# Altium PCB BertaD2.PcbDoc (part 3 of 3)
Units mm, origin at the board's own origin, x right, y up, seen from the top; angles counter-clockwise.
Board outline 100.5 x 100 mm, 4 copper layers (Top Layer, Signal Layer 1, Signal Layer 2, Bottom Layer), stack 0.778 mm thick; 108 components, 216 nets, 850 pads, 807 vias.
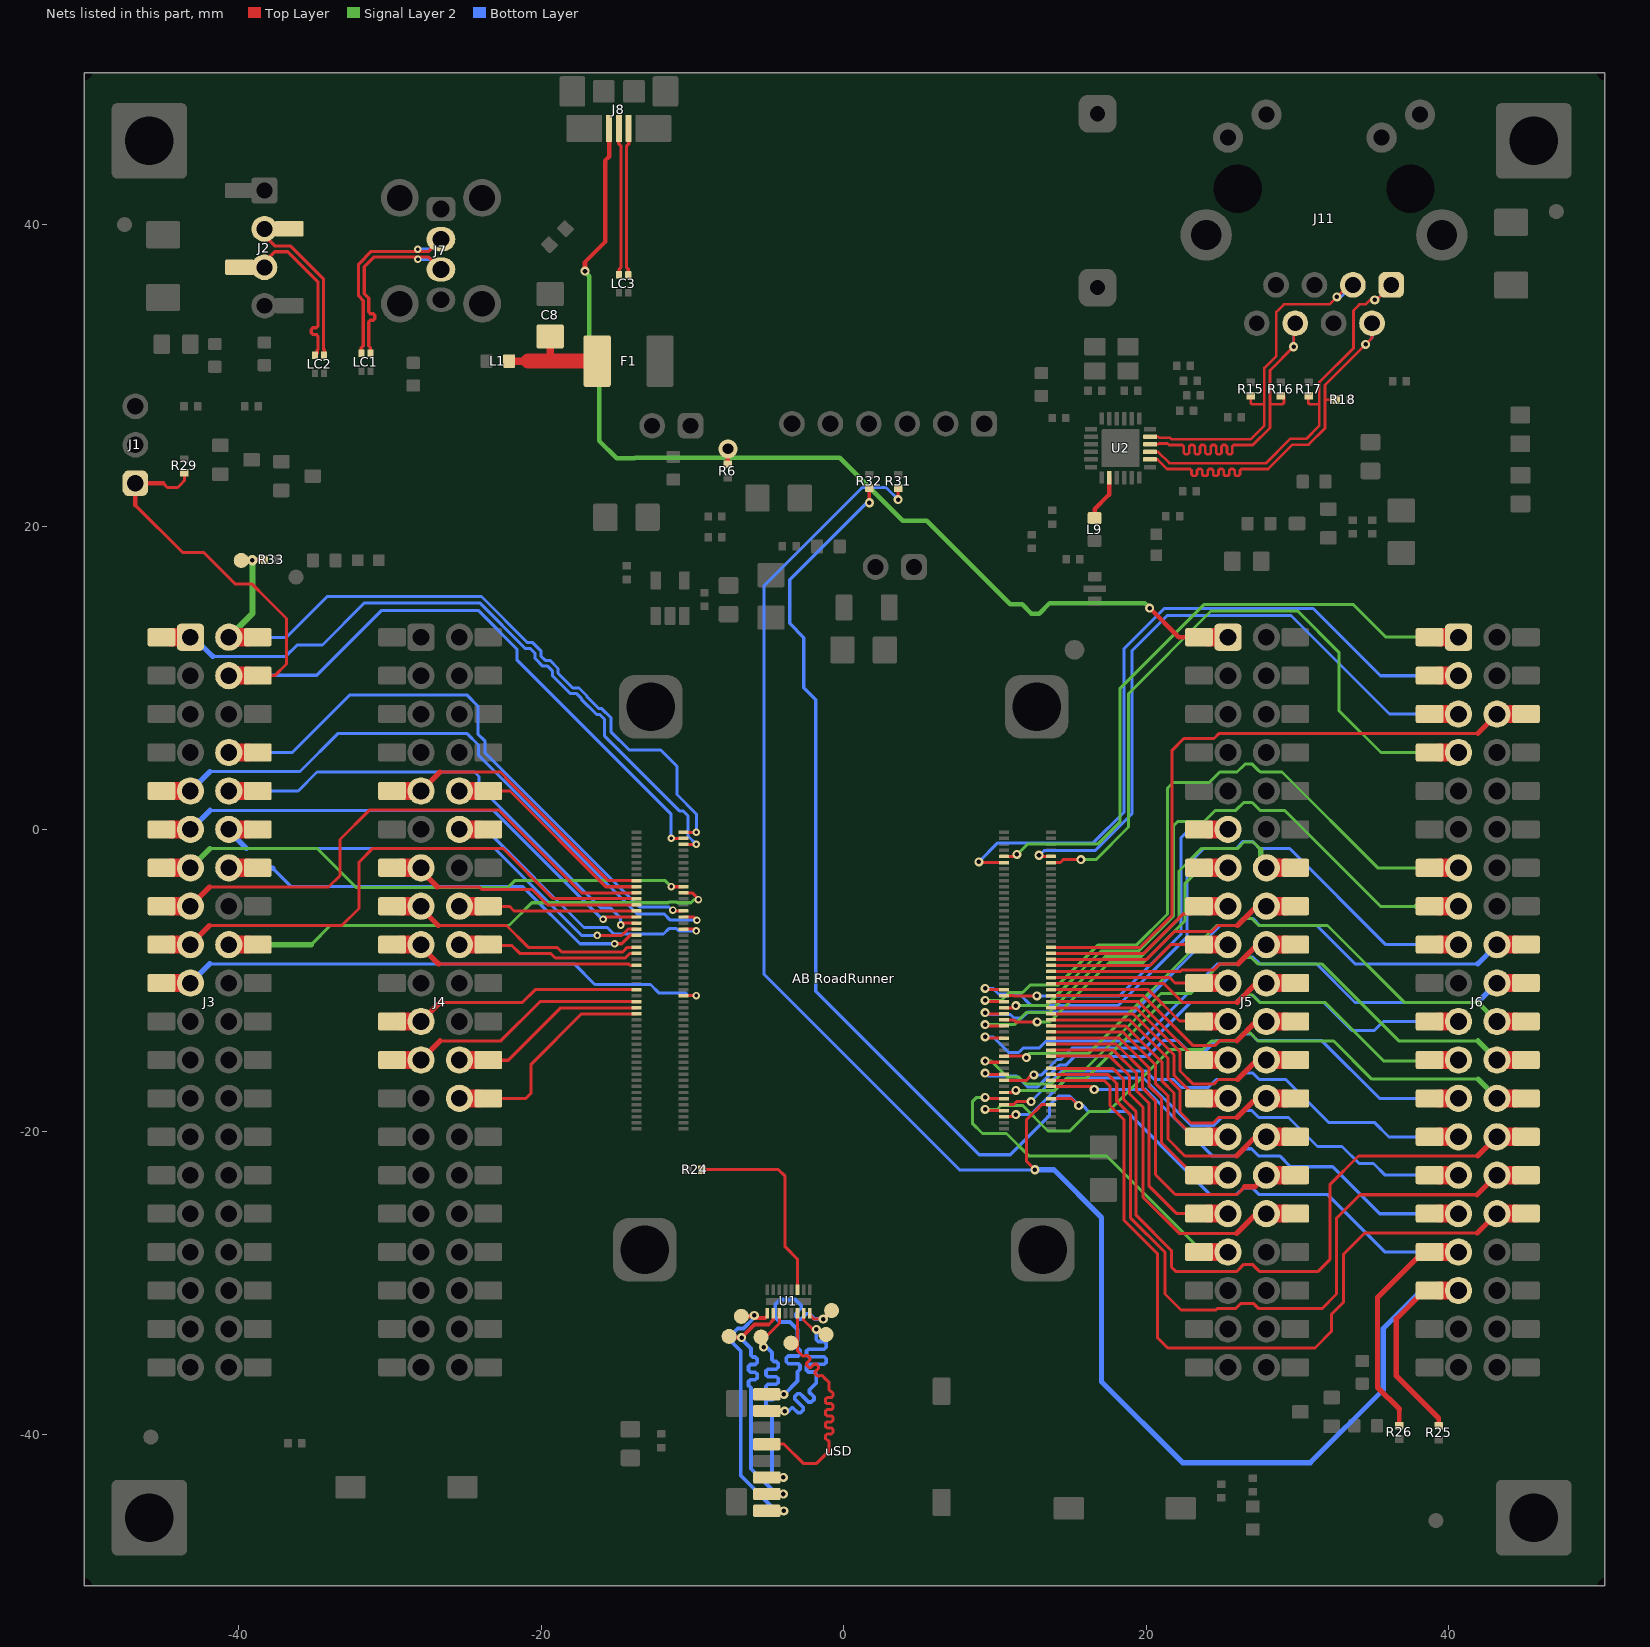
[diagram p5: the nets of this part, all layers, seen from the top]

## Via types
v1: diameter 0.5, hole 0.25, Top Layer to Bottom Layer, tented both sides, 469 vias
v2: diameter 0.6, hole 0.3, Top Layer to Bottom Layer, tented both sides, 200 vias
v3: diameter 1.27, hole 0.7, Top Layer to Bottom Layer, tented both sides, 72 vias
v4: diameter 0.7, hole 0.3, Top Layer to Bottom Layer, tented both sides, 20 vias
v5: diameter 0.9, hole 0.5, Top Layer to Bottom Layer, tented both sides, 19 vias
v6: diameter 0.7, hole 0.3, Top Layer to Bottom Layer, 8 vias
v7: diameter 1, hole 0.5, Top Layer to Bottom Layer, tented both sides, 6 vias
v8: diameter 1.7, hole 1.05, Top Layer to Bottom Layer, tented both sides, 5 vias
v9: diameter 3, hole 1.5, Top Layer to Bottom Layer, 3 vias
v10: diameter 1.7, hole 1.05, Top Layer to Bottom Layer, 3 vias
v11: diameter 0.56, hole 0.3, Top Layer to Bottom Layer, tented both sides, 1 vias
v12: diameter 0.8, hole 0.4, Top Layer to Bottom Layer, tented both sides, 1 vias

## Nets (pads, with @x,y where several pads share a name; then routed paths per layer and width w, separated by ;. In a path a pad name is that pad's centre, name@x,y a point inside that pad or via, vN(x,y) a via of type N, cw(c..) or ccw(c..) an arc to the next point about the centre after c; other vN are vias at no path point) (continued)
PC1: "AB RoadRunner.J1-61" J4.26 | length 15.1
  Top Layer w0.2: J4.26@-25.4,-17.8 -23.485,-17.8 -21.03,-17.8 -20.66,-17.43 -20.66,-15.52 -17.333,-12.193 -13.705,-12.193
PC2: "AB RoadRunner.J1-59" J4.24 | length 11.2
  Top Layer w0.2: J4.24@-23.485,-15.26 -22.17,-15.26 -18.703,-11.792 -13.705,-11.792
PC3: "AB RoadRunner.J1-57" J4.23 | length 15.8
  Top Layer w0.2: -26.68,-13.98 -22.66,-13.98 -20.072,-11.392 -13.705,-11.392
  Top Layer w0.35: J4.23@-27.94,-15.24 -26.68,-13.98
PC4: "AB RoadRunner.J1-53" J4.21 | length 15.1
  Top Layer w0.2: -26.675,-11.435 -21.235,-11.435 -20.392,-10.592 -13.705,-10.592
  Top Layer w0.35: J4.21@-27.94,-12.7 -26.675,-11.435
PC5: "AB RoadRunner.J1-39" J4.15 | length 15.7
  Top Layer w0.2: -26.799,-6.351 -22.289,-6.351 -20.848,-7.792 -18.949,-7.792 -18.635,-8.107 -15.369,-8.107 -15.367,-8.109 -14.913,-8.109 -14.911,-8.107 -14.612,-8.107 -14.297,-7.792 -13.705,-7.792
  Top Layer w0.35: J4.15@-28.005,-5.145 -26.799,-6.351
PC6: "AB RoadRunner.J1-41" J4.18 | length 12.3
  Top Layer w0.2: J4.18@-25.49,-7.86 -25.325,-7.695 -25.3,-7.67 -23.485,-7.67 -21.94,-7.67 -21.417,-8.193 -19.377,-8.193 -19.063,-8.506 -15.535,-8.506 -15.533,-8.508 -14.747,-8.508 -14.745,-8.506 -14.435,-8.506 -14.122,-8.193 -13.705,-8.193
PC7: "AB RoadRunner.J1-45" J4.17 | length 14.8
  Top Layer w0.2: -26.77,-8.89 -19.871,-8.89 -19.854,-8.907 -19.247,-8.907 -19.245,-8.905 -15.7,-8.905 -15.698,-8.907 -14.582,-8.907 -14.58,-8.905 -14.192,-8.905 -14.105,-8.991 -13.706,-8.991 -13.705,-8.992
  Top Layer w0.35: J4.17@-27.99,-7.67 -26.77,-8.89
PC8: "AB RoadRunner.J1-56" J3.19 | length 35.7
  Top Layer w0.2: -10.595,-10.993 v1@-9.742,-10.993
  Bottom Layer w0.2: -41.91,-8.89 -17.81,-8.89 -16.45,-10.25 -12.775,-10.25 -12.225,-10.8 -10.45,-10.8 -10.26,-10.99 v1(-9.74,-10.99)
  Bottom Layer w0.35: J3.19@-43.18,-10.16 -41.91,-8.89
PC9: "AB RoadRunner.J2-40" J6.6 | length 42.3
  Top Layer w0.2: 13.705,-7.792 19.592,-7.792 ; 19.592,-7.791 21.715,-5.668 21.715,5.233 22.484,6.002 24.482,6.002 24.831,6.351 41.931,6.351
  Top Layer w0.35: 41.931,6.351 J6.6@43.19,7.61
PC10: "AB RoadRunner.J2-52" J5.20 | length 15.3
  Top Layer w0.2: 13.705,-10.191 21.162,-10.191 22.399,-11.429 26.011,-11.429 ; J5.20@27.215,-10.225 27.94,-10.225 J5.20@28.005,-10.225
  Top Layer w0.35: 26.011,-11.429 J5.20@27.215,-10.225
PC11: "AB RoadRunner.J2-50" J5.19 | length 11.8
  Top Layer w0.2: 13.705,-9.792 21.543,-9.792 21.9,-10.15 23.485,-10.15 J5.19@25.4,-10.15
PC12: "AB RoadRunner.J2-48" J5.18 | length 15
  Top Layer w0.2: 13.705,-9.392 22.257,-9.392 22.37,-9.28 24.46,-9.28 24.85,-8.89 26.07,-8.89 ; J5.18@27.33,-7.63 27.94,-7.63 J5.18@27.95,-7.63
  Top Layer w0.35: 26.07,-8.89 J5.18@27.33,-7.63
PC13: "AB RoadRunner.J2-46" J5.17 | length 12.2
  Top Layer w0.2: 13.705,-8.992 20.255,-8.992 ; 20.255,-8.991 21.647,-7.599 ; 21.647,-7.6 23.485,-7.6 J5.17@25.31,-7.6
PC14: "AB RoadRunner.J2-44" J5.16 | length 15.7
  Top Layer w0.2: 13.705,-8.592 20.038,-8.592 ; 20.038,-8.591 21.891,-6.739 ; 21.891,-6.74 24.35,-6.74 24.73,-6.36 26.02,-6.36 ; J5.16@27.345,-5.035 J5.16@27.895,-5.035
  Top Layer w0.35: 26.02,-6.36 J5.16@27.345,-5.035
PC15: "AB RoadRunner.J2-42" J5.15 | length 12.6
  Top Layer w0.2: 13.705,-8.193 19.83,-8.193 ; 19.83,-8.191 22.443,-5.579 ; 22.443,-5.58 22.985,-5.58 J5.15@23.485,-5.08 24.1,-5.08 J5.15@25.06,-5.08
PC16: "AB RoadRunner.J2-64" J5.26 | length 19.1
  Top Layer w0.2: 13.705,-12.591 18.892,-12.591 ; 18.892,-12.592 21.43,-15.13 21.43,-16.444 22.233,-17.247 22.233,-18.683 22.96,-19.41 24.42,-19.41 24.781,-19.049 26.001,-19.049 ; J5.26@27.095,-17.955 J5.26@27.785,-17.955
  Top Layer w0.35: 26.001,-19.049 J5.26@27.095,-17.955
PC17: "AB RoadRunner.J2-62" J5.25 | length 12.7
  Top Layer w0.2: 13.705,-12.191 19.118,-12.191 ; 19.118,-12.193 21.83,-14.904 21.83,-16.256 23.13,-17.556 J5.25@23.13,-17.77
PC18: "AB RoadRunner.J2-60" J5.24 | length 17.8
  Top Layer w0.2: 13.705,-11.791 19.315,-11.791 ; 19.315,-11.792 22.23,-14.707 22.23,-15.965 23.111,-16.846 24.454,-16.846 24.77,-16.53 26.03,-16.53 ; J5.24@27.24,-15.32 27.94,-15.32 J5.24@28.02,-15.32
  Top Layer w0.35: 26.03,-16.53 J5.24@27.24,-15.32
PC19: "AB RoadRunner.J2-58" J5.23 | length 10.7
  Top Layer w0.2: 13.705,-11.391 19.493,-11.391 J5.23@22.945,-14.845
PC20: "AB RoadRunner.J2-56" J5.22 | length 16.3
  Top Layer w0.2: 13.705,-10.991 19.804,-10.991 23.112,-14.3 24.52,-14.3 24.85,-13.97 26,-13.97 ; J5.22@27.265,-12.705 27.94,-12.705 J5.22@27.945,-12.705
  Top Layer w0.35: 26,-13.97 J5.22@27.265,-12.705
PC21: "AB RoadRunner.J2-54" J5.21 | length 12.6
  Top Layer w0.2: 13.705,-10.592 20.127,-10.592 22.194,-12.66 23.485,-12.66 J5.21@25.4,-12.66
PC22: "AB RoadRunner.J2-76" J5.32 | length 23.8
  Top Layer w0.2: 13.705,-14.991 17.592,-14.991 ; 17.592,-14.992 18.902,-16.302 18.902,-17.486 19.79,-18.374 19.79,-24.31 22.18,-26.7 25.97,-26.7 ; J5.32@27.317,-25.353 J5.32@27.893,-25.353
  Top Layer w0.35: 25.97,-26.7 J5.32@27.317,-25.353
PC23: "AB RoadRunner.J2-74" J5.31 | length 19.1
  Top Layer w0.2: 13.705,-14.591 17.823,-14.591 ; 17.823,-14.593 19.35,-16.12 19.35,-17.281 20.191,-18.122 20.191,-23.581 21.987,-25.378 23.485,-25.378 24.42,-25.378
PC24: "AB RoadRunner.J2-72" J5.30 | length 22.1
  Top Layer w0.2: 13.705,-14.191 18.002,-14.191 ; 18.002,-14.192 19.76,-15.95 19.76,-17.112 20.61,-17.962 20.61,-22.82 21.92,-24.13 26.01,-24.13 26.51,-23.63
  Top Layer w0.35: 26.51,-23.63 27.17,-23.63 J5.30@27.76,-23.04
PC25: "AB RoadRunner.J2-70" J5.29 | length 15.5
  Top Layer w0.2: 13.705,-13.791 18.223,-13.791 ; 18.223,-13.792 20.17,-15.74 20.17,-16.937 21.017,-17.784 21.017,-20.727 J5.29@23.075,-22.785
PC26: "AB RoadRunner.J2-68" J5.28 | length 20.6
  Top Layer w0.2: 13.705,-13.391 18.453,-13.391 ; 18.453,-13.393 20.6,-15.54 20.6,-16.772 21.43,-17.602 21.43,-20.47 22.55,-21.59 25.96,-21.59 ; J5.28@27.205,-20.345 27.94,-20.345 J5.28@27.965,-20.345
  Top Layer w0.35: 25.96,-21.59 J5.28@27.205,-20.345
PC27: "AB RoadRunner.J2-66" J5.27 | length 14.1
  Top Layer w0.2: 13.705,-12.992 18.643,-12.992 ; 18.643,-12.993 21.03,-15.38 21.03,-16.623 21.831,-17.424 21.831,-19.031 J5.27@23.14,-20.34
PC28: "AB RoadRunner.J2-57" J6.13 | length 46.7
  Top Layer w0.2: v2(9.35,-11.31) 9.432,-11.392 10.595,-11.392
  Signal Layer 2 w0.2: v2(9.35,-11.31) 10.42,-11.31 10.944,-10.786 11.833,-10.786 12.319,-10.3 14.157,-10.3 16.797,-7.66 19.34,-7.66 21.41,-5.59 21.41,2.72 21.79,3.1 24.17,3.1 24.86,3.79 26,3.79 26.52,4.31 27.013,4.31 27.443,3.88 27.45,3.88 27.54,3.79 28.97,3.79 35.3,-2.54 38.08,-2.54
  Signal Layer 2 w0.35: 38.08,-2.54 J6.13@40.64,-2.54
PC29: "AB RoadRunner.J2-59" J6.15 | length 42.5
  Top Layer w0.2: 10.788,-11.792 10.595,-11.792 11.238,-11.792 v2(11.38,-11.65)
  Signal Layer 2 w0.2: v2(11.38,-11.65) 13.395,-11.65 17.005,-8.04 19.497,-8.04 21.79,-5.747 21.79,0.24 22.06,0.51 23.82,0.51 24.57,1.26 25.92,1.26 26.44,1.78 27.003,1.78 27.523,1.26 29.13,1.26 35.494,-5.104 38.1,-5.104
  Signal Layer 2 w0.35: 37.841,-5.08 J6.15@40.64,-5.08
PC30: "AB RoadRunner.J2-63" J5.13 | length 20.5
  Top Layer w0.2: 10.595,-12.593 11.045,-12.592 11.238,-12.592 11.365,-12.72 v2(12.78,-12.72)
  Signal Layer 2 w0.2: v2(12.78,-12.72) 13.642,-12.72 17.562,-8.8 19.812,-8.8 22.55,-6.062 22.55,-3.59 23.59,-2.55
  Signal Layer 2 w0.35: 23.59,-2.55 J5.13@25.4,-2.55
PC31: "AB RoadRunner.J2-65" J5.14 | length 28.2
  Top Layer w0.2: v2(9.35,-12.91) 9.432,-12.992 10.595,-12.992
  Signal Layer 2 w0.2: v2(9.35,-12.91) 11.27,-12.91 12.09,-12.09 13.604,-12.09 17.274,-8.42 19.655,-8.42 22.17,-5.905 22.17,-2.75 23.67,-1.25 26.05,-1.25 26.46,-0.84 27.07,-0.84 27.575,-1.345 ; J5.14@27.575,-1.882 27.94,-2.247 J5.14@27.94,-2.54 ; J5.14@27.92,-2.88 J5.14@27.92,-2.54
  Signal Layer 2 w0.35: J5.14@27.575,-1.882 27.575,-1.345
PD0: "AB RoadRunner.J2-69" J6.20 | length 39.9
  Top Layer w0.2: v2(9.35,-13.71) 9.432,-13.792 10.595,-13.792
  Bottom Layer w0.2: v2(9.35,-13.71) 9.862,-13.71 10.907,-14.755 11.565,-14.755 11.868,-14.452 12.929,-14.452 13.4,-13.981 19.613,-13.981 24.704,-8.89 26.07,-8.89 26.53,-8.43 27.053,-8.43 27.513,-8.89 31.25,-8.89 33.8,-11.44 41.9,-11.44
  Bottom Layer w0.35: 41.9,-11.44 J6.20@43.18,-10.16
PD1: "AB RoadRunner.J2-61" J6.18 | length 39.7
  Top Layer w0.2: v2(9.35,-12.11) 9.432,-12.193 10.595,-12.193
  Bottom Layer w0.2: v2(9.35,-12.11) 9.47,-12.23 11.02,-12.23 11.262,-12.472 11.79,-12.472 12.206,-12.056 19.204,-12.056 24.9,-6.36 26.05,-6.36 26.51,-5.9 27.063,-5.9 27.523,-6.36 31.27,-6.36 33.801,-8.891 41.909,-8.891
  Bottom Layer w0.35: 41.909,-8.891 J6.18@43.18,-7.62
PD2_URXD1: "AB RoadRunner.J2-90" J6.33 R26.1 R32.2 | length 105.5
  Top Layer w0.2: 13.705,-17.792 15.052,-17.792 v2@15.511,-18.251
  Top Layer w0.22: v2(1.7,21.59) R32.2@1.7,22.55 ; v2@15.511,-18.251 v2(15.538,-18.251)
  Top Layer w0.3: R26.1@36.73,-39.32 36.73,-38.32
  Top Layer w0.35: 36.73,-38.32 35.29,-36.88 35.29,-30.93 38.28,-27.94 J6.33@38.725,-27.94
  Bottom Layer w0.22: v2(1.7,21.59) 1.53,21.59 -3.57,16.49 -3.57,13.61 -2.64,12.68 -2.64,9.37 -1.84,8.57 -1.84,-10.711 8.949,-21.5 11.02,-21.5 13.6,-18.92 13.6,-18.25 14.21,-17.64 14.927,-17.64 v2(15.538,-18.251) 15.806,-18.251 16.207,-18.652 18.732,-18.652 24.21,-24.13 25.99,-24.13 26.44,-23.68 26.99,-23.68 27.44,-24.13 31.97,-24.13 35.78,-27.94 38.384,-27.94
  Bottom Layer w0.35: 38.384,-27.94 J6.33@40.64,-27.94
PD3_UTXD1: "AB RoadRunner.J2-92" J6.35 R25.1 R31.2 | length 127.8
  Top Layer w0.2: v2(3.6,21.8) R31.2@3.6,22.55 ; v2(12.64,-22.5) 12.092,-21.952 12.092,-19.18 12.681,-18.591 12.685,-18.591 13.083,-18.192 13.705,-18.192
  Top Layer w0.3: R25.1@39.32,-39.43 39.32,-38.92
  Top Layer w0.35: J6.35@38.725,-30.48 38.4,-30.48 36.53,-32.35 36.53,-36.13 39.32,-38.92
  Bottom Layer w0.2: v2(3.6,21.8) 2.8,22.6 1.22,22.6 -5.26,16.12 -5.26,-9.59 7.65,-22.5 v2(12.64,-22.5)
  Bottom Layer w0.35: v2(12.64,-22.5) 13.89,-22.5 17.04,-25.65 17.04,-36.51 22.39,-41.86 30.84,-41.86 35.66,-37.04 35.66,-32.996 38.176,-30.48 J6.35@40.64,-30.48 J6.35@40.649,-30.48
PD4: "AB RoadRunner.J2-55" J5.11 | length 23.1
  Top Layer w0.2: 10.595,-10.993 10.788,-10.993 ; 10.795,-11 10.788,-10.993 ; 11.238,-10.992 11.045,-10.992 10.788,-10.993 ; 11.245,-11 v2(12.77,-11)
  Bottom Layer w0.2: v2(12.77,-11) 18.235,-11 22.297,-6.938 22.297,-0.553 22.844,-0.006 J5.11@25.4,-0.006
PD5: "AB RoadRunner.J2-53" J6.17 | length 43.1
  Top Layer w0.2: v2(9.35,-10.51) 9.432,-10.592 10.595,-10.592
  Bottom Layer w0.2: v2(9.35,-10.51) 9.858,-10.51 10.233,-10.885 11.626,-10.885 12.373,-11.632 18.167,-11.632 22.7,-7.099 22.7,-2.38 23.81,-1.27 25.93,-1.27 26.41,-0.79 27,-0.79 27.48,-1.27 29.48,-1.27 35.83,-7.62 38.391,-7.62
  Bottom Layer w0.35: 38.391,-7.62 J6.17@40.64,-7.62
PD6: "AB RoadRunner.J2-86" J6.31 | length 30.8
  Top Layer w0.2: 13.705,-16.992 v2@16.355,-16.992 ; v2@16.355,-16.988 v2(16.56,-17.193)
  Bottom Layer w0.2: v2(16.56,-17.193) 19.927,-17.193 19.95,-17.17 24.36,-21.58 25.97,-21.58 26.44,-21.11 26.95,-21.11 27.42,-21.58 28.82,-21.58 29.54,-22.3 32.32,-22.3 35.426,-25.406 38.413,-25.406
  Bottom Layer w0.35: 38.413,-25.406 J6.31@40.64,-25.406
PD7: "AB RoadRunner.J2-84" J6.32 | length 50.9
  Top Layer w0.2: 13.705,-16.592 17.22,-16.592 17.605,-16.977 17.605,-18.265 18.52,-19.18 18.52,-25.82 20.73,-28.03 20.73,-33.583 21.427,-34.28 31.15,-34.28 32.25,-33.18 32.25,-32.05 33.04,-31.26 33.04,-28.08 34.44,-26.68 41.88,-26.68
  Top Layer w0.35: 41.88,-26.68 J6.32@43.17,-25.39
PD8: "AB RoadRunner.J2-80" J6.28 | length 47.4
  Top Layer w0.2: 13.705,-15.792 17.776,-15.792 ; 17.776,-15.793 18.496,-16.512 18.496,-17.836 19.33,-18.67 19.33,-25.51 21.672,-27.852 21.672,-28.942 21.94,-29.21 25.99,-29.21 26.45,-28.75 27.01,-28.75 27.47,-29.21 31.36,-29.21 32.13,-28.44 32.13,-23.49 34.03,-21.59 41.9,-21.59
  Top Layer w0.35: 41.9,-21.59 J6.28@43.175,-20.315
PD9: "AB RoadRunner.J2-77" J6.24 | length 42
  Top Layer w0.2: v2(9.35,-15.31) 9.432,-15.392 10.595,-15.392
  Signal Layer 2 w0.2: v2(9.35,-15.31) 9.76,-15.31 10.82,-16.37 11.58,-16.37 12.038,-16.828 13.736,-16.828 14.619,-15.945 15.881,-15.945 20.976,-10.85 22.94,-10.85 24.9,-8.89 26.03,-8.89 26.44,-8.48 26.96,-8.48 27.37,-8.89 31.59,-8.89 36.68,-13.98 41.92,-13.98
  Signal Layer 2 w0.35: 41.92,-13.98 J6.24@43.18,-15.24
PD10: "AB RoadRunner.J2-82" J6.30 | length 49.1
  Top Layer w0.2: 13.705,-16.192 17.449,-16.192 ; 17.449,-16.193 18.048,-16.792 18.048,-17.975 18.945,-18.872 18.945,-25.662 21.235,-27.952 21.235,-30.705 22.3,-31.77 24.605,-31.77 24.695,-31.68 25.897,-31.68 26.227,-31.35 27.113,-31.35 27.443,-31.68 31.61,-31.68 32.579,-30.711 32.579,-25.701 34.13,-24.15 41.86,-24.15
  Top Layer w0.35: 41.86,-24.15 J6.30@43.165,-22.845
PD11: "AB RoadRunner.J2-95" J6.29 | length 34.6
  Top Layer w0.2: 10.595,-18.993 11.238,-18.993 v2(11.38,-18.85)
  Bottom Layer w0.2: v2(11.38,-18.85) 12.36,-18.85 14.78,-16.43 19.822,-16.43 22.952,-19.56 24.463,-19.56 24.963,-19.06 25.95,-19.06 26.44,-18.57 26.96,-18.57 27.439,-19.049 29.406,-19.049 31.317,-20.96 32.94,-20.96 34.07,-22.09 35.02,-22.09 35.79,-22.86 38.463,-22.86
  Bottom Layer w0.35: 38.463,-22.86 J6.29@40.64,-22.86
PD12: "AB RoadRunner.J2-75" J6.22 | length 39.2
  Top Layer w0.2: 10.595,-14.993 v2@12.02,-14.993
  Signal Layer 2 w0.2: v2(12.079,-15.09) 12.079,-15.001 12.275,-14.805 16.202,-14.805 24.647,-6.36 25.93,-6.36 26.41,-5.88 26.95,-5.88 27.43,-6.36 31.98,-6.36 37.05,-11.43 41.91,-11.43
  Signal Layer 2 w0.35: 41.91,-11.43 J6.22@43.18,-12.7
PD13: "AB RoadRunner.J2-93" J6.26 | length 40.4
  Top Layer w0.2: v2(9.35,-18.51) 9.432,-18.593 10.595,-18.593
  Signal Layer 2 w0.2: v2(9.35,-18.51) 10.13,-18.51 10.4,-18.24 11.814,-18.24 13.504,-19.93 14.95,-19.93 16.23,-18.65 17.478,-18.65 21.578,-14.55 23.74,-14.55 24.3,-13.99 25.85,-13.99 26.39,-13.45 26.85,-13.45 27.39,-13.99 32.39,-13.99 34.909,-16.509 41.924,-16.509
  Signal Layer 2 w0.35: 41.924,-16.509 J6.26@43.188,-17.772
PD14: "AB RoadRunner.J2-83" J6.21 | length 33.5
  Top Layer w0.2: 10.595,-16.593 12.067,-16.593 12.438,-16.222 v2(12.567,-16.222)
  Bottom Layer w0.2: v2(12.567,-16.222) 13.082,-16.222 14.098,-15.206 14.351,-15.206 15.097,-14.46 19.907,-14.46 22.938,-11.429 25.941,-11.429 26.37,-11 27.083,-11 27.512,-11.429 31.739,-11.429 33.59,-13.28 35.09,-13.28 35.67,-12.7 38.196,-12.7
  Bottom Layer w0.35: 38.196,-12.7 J6.21@40.64,-12.7
PD15: "AB RoadRunner.J2-81" J6.25 | length 36.7
  Top Layer w0.2: v2(9.35,-16.11) 9.432,-16.192 10.595,-16.192
  Bottom Layer w0.2: v2(9.35,-16.11) 9.543,-16.303 11.43,-16.303 12.147,-17.02 12.822,-17.02 14.256,-15.586 14.684,-15.586 15.244,-15.026 20.067,-15.026 21.123,-13.97 22.08,-13.97 22.65,-14.54 24.03,-14.54 24.6,-13.97 25.97,-13.97 26.42,-13.52 26.92,-13.52 27.37,-13.97 31.6,-13.97 35.41,-17.78 38.382,-17.78
  Bottom Layer w0.35: 38.382,-17.78 J6.25@40.64,-17.78 J6.25@40.686,-17.78
PD16: "AB RoadRunner.J2-91" J6.27 | length 33.7
  Top Layer w0.2: 10.595,-18.193 11.238,-18.193 11.438,-17.992 v2(12.387,-17.992)
  Bottom Layer w0.2: v2@12.385,-18.075 12.387,-18.073 v2(12.387,-17.992) 14.413,-15.966 19.968,-15.966 20.532,-16.53 21.799,-16.53 22.329,-17.06 24.096,-17.06 24.626,-16.53 26.04,-16.53 26.47,-16.1 27.04,-16.1 27.47,-16.53 29.22,-16.53 32.05,-19.36 35.07,-19.36 36.046,-20.336 38.486,-20.336
  Bottom Layer w0.35: 38.486,-20.336 J6.27@40.64,-20.336
PD17: "AB RoadRunner.J2-87" J6.23 | length 34.5
  Top Layer w0.2: 10.595,-17.393 v2@11.238,-17.393
  Signal Layer 2 w0.2: v2(11.38,-17.25) 13.945,-17.25 14.738,-16.457 16.034,-16.457 21.051,-11.44 25.92,-11.44 26.41,-10.95 27.01,-10.95 27.5,-11.44 31.83,-11.44 35.694,-15.304 38.081,-15.304
  Signal Layer 2 w0.35: 38.081,-15.304 40.617,-15.304 J6.23@40.77,-15.457
PD18: "AB RoadRunner.J2-89" J5.33 | length 24.1
  Top Layer w0.2: v2(9.35,-17.71) 9.432,-17.792 10.595,-17.792
  Signal Layer 2 w0.2: v2(9.35,-17.71) 8.79,-17.71 8.5,-18 8.5,-19.43 9.17,-20.1 10.759,-20.1 12.259,-21.6 17.4,-21.6 23.7,-27.9 24,-27.9
  Signal Layer 2 w0.4: 24,-27.9 J5.33@25.4,-27.9
PD19: "AB RoadRunner.J2-9" J6.1 | length 43.4
  Top Layer w0.2: 10.788,-1.793 10.595,-1.793 11.407,-1.793 11.45,-1.75 v2(11.45,-1.65)
  Signal Layer 2 w0.2: v2@11.38,-1.75 11.465,-1.665 12.15,-0.98 16.79,-0.98 18.25,0.48 18.25,9.3 23.806,14.856 33.694,14.856 35.85,12.7 38.647,12.7
  Signal Layer 2 w0.35: 38.647,12.7 J6.1@40.64,12.7
PD20: "AB RoadRunner.J2-11" J6.3 | length 48.4
  Top Layer w0.2: v2@8.93,-2.193 10.525,-2.193
  Bottom Layer w0.2: v2(8.93,-2.15) 10.189,-0.891 16.501,-0.891 18.541,1.149 18.541,11.957 21.184,14.6 31.03,14.6 35.476,10.154 38.248,10.154
  Bottom Layer w0.35: 38.248,10.154 J6.3@40.64,10.154
PD21: "AB RoadRunner.J2-10" J6.5 | length 44
  Top Layer w0.2: v2@12.992,-1.793 13.705,-1.793
  Bottom Layer w0.2: v2(12.91,-1.71) 12.937,-1.71 13.255,-1.392 16.628,-1.392 19.07,1.05 19.07,11.82 21.38,14.13 29.57,14.13 36.08,7.62 38.08,7.62
  Bottom Layer w0.35: 38.08,7.62 J6.5@40.64,7.62
PD22: "AB RoadRunner.J2-12" J6.7 | length 45.2
  Top Layer w0.2: 13.705,-2.193 14.327,-2.193 14.539,-1.981 14.554,-1.996 v2(15.683,-1.996)
  Signal Layer 2 w0.2: v2(15.683,-1.996) 16.62,-1.996 16.623,-1.999 16.646,-1.976 16.67,-2 18.82,0.15 18.82,8.97 24.284,14.434 30.006,14.434 32.73,11.71 32.73,7.86 35.51,5.08 38.246,5.08
  Signal Layer 2 w0.35: 38.246,5.08 J6.7@40.64,5.08
PD23: "AB RoadRunner.J1-28" J3.8 | length 39
  Top Layer w0.2: v1@-11.29,-5.392 -10.595,-5.392
  Bottom Layer w0.2: -38.965,5.08 -36.44,5.08 -32.63,8.89 -24.91,8.89 -24.18,8.16 -24.18,6.31 -23.72,5.85 -23.72,5.08 -13.51,-5.13 -11.55,-5.13 -11.346,-5.334 v1(-11.29,-5.334)
  Bottom Layer w0.35: J3.8@-40.64,5.08 -38.965,5.08
PD24: "AB RoadRunner.J1-30" J3.9 | length 41.5
  Top Layer w0.2: -10.595,-5.793 -9.907,-5.793 v1(-9.7,-6)
  Bottom Layer w0.2: -41.884,3.82 -35.94,3.82 -33.41,6.35 -24.92,6.35 -24.14,5.57 -24.14,4.9 -13.656,-5.584 -11.876,-5.584 -11.46,-6 v1(-9.7,-6)
  Bottom Layer w0.35: J3.9@-43.172,2.532 -41.884,3.82
PD25: "AB RoadRunner.J1-34" J4.12 | length 19.6
  Top Layer w0.2: -10.595,-6.592 -9.75,-6.592 v1@-9.742,-6.592
  Bottom Layer w0.2: J4.12@-25.4,0 -23.65,0 -17.17,-6.48 -15.62,-6.48 -15.191,-6.909 -11.909,-6.909 -11.56,-6.56 -11.05,-6.56 -10.9,-6.71 v1(-9.75,-6.71)
PD26: "AB RoadRunner.J1-25" J4.13 | length 15.3
  Top Layer w0.2: -26.86,-3.81 -24.08,-3.81 -23.92,-3.97 -20.587,-3.97 -19.565,-4.992 -13.705,-4.992
  Top Layer w0.35: J4.13@-28.035,-2.635 -26.86,-3.81
PD27: "AB RoadRunner.J1-27" J4.16 | length 12
  Top Layer w0.2: J4.16@-25.45,-5.34 -25.295,-5.185 -25.2,-5.09 -23.485,-5.09 -22.09,-5.09 -21.788,-5.392 -13.705,-5.392
PD28: "AB RoadRunner.J1-29" J3.11 | length 33
  Top Layer w0.2: v1(-15.9,-5.942) -15.9,-5.92 -15.77,-5.79 -13.705,-5.79
  Bottom Layer w0.2: -41.883,1.26 -23.157,1.26 -15.955,-5.942 v1(-15.9,-5.942)
  Bottom Layer w0.35: J3.11@-43.162,-0.018 -41.883,1.26
PD29: "AB RoadRunner.J1-31" J3.10 | length 32.3
  Top Layer w0.2: v1(-14.74,-6.32) -14.612,-6.192 -13.705,-6.192
  Bottom Layer w0.2: -38.924,2.54 -36.06,2.54 -34.81,3.79 -24.4,3.79 -24.1,3.49 -24.1,2.854 -16.041,-5.205 -15.405,-5.205 -14.74,-5.87 v1(-14.74,-6.32)
  Bottom Layer w0.35: J3.10@-40.64,2.54 -38.924,2.54
PD30: "AB RoadRunner.J1-33" J3.12 | length 30.1
  Top Layer w0.2: v1(-16.29,-7.01) -14.677,-7.01 -14.259,-6.592 -13.705,-6.592
  Bottom Layer w0.2: -39.468,-1.27 -24.72,-1.27 -24.7,-1.25 -23.08,-1.25 -17.32,-7.01 v1(-16.29,-7.01)
  Bottom Layer w0.35: J3.12@-40.689,-0.049 -39.468,-1.27
PD31: "AB RoadRunner.J1-35" J3.14 | length 29.2
  Top Layer w0.2: v1(-15.14,-7.56) -14.672,-7.56 -14.104,-6.993 -13.705,-6.993
  Bottom Layer w0.2: -37.732,-2.571 -36.513,-3.79 -21.206,-3.79 -17.436,-7.56 v1(-15.14,-7.56)
  Bottom Layer w0.35: J3.14@-40.64,-2.571 -37.732,-2.571
PIOBU2: "AB RoadRunner.J1-20" J3.13 | length 34.6
  Top Layer w0.2: v1@-11.447,-3.792 -11.4,-3.792 -10.595,-3.792
  Signal Layer 2 w0.2: -41.899,-1.27 -41.886,-1.27 -34.79,-1.27 -32.219,-3.841 -22.205,-3.841 -21.752,-3.388 -11.792,-3.388 v1(-11.4,-3.78)
  Signal Layer 2 w0.35: J3.13@-43.168,-2.552 -41.886,-1.27
PIOBU3: "AB RoadRunner.J1-22" J3.18 | length 33.5
  Top Layer w0.2: -10.595,-4.192 -10.018,-4.192 -9.6,-4.61 v1(-9.6,-4.64)
  Signal Layer 2 w0.2: -35.2,-7.62 -33.94,-6.36 -22.12,-6.36 -20.61,-4.85 -11.582,-4.85 -11.517,-4.785 -11.063,-4.785 -10.998,-4.85 -10.09,-4.85 -9.88,-4.64 v1(-9.6,-4.64)
  Signal Layer 2 w0.35: J3.18@-40.645,-7.62 J3.18@-40.64,-7.62 -35.2,-7.62
PIOBU4: "AB RoadRunner.J1-17" J4.9 | length 17.8
  Top Layer w0.2: -26.69,3.79 -22.683,3.79 -22.359,3.466 -22.359,3.413 -15.554,-3.393 -13.705,-3.393
  Top Layer w0.35: J4.9@-27.94,2.54 -26.69,3.79
PIOBU5: "AB RoadRunner.J1-19" J4.10 | length 14.3
  Top Layer w0.2: J4.10@-25.4,2.54 -24.1,2.54 J4.10@-23.485,2.54 -22.051,2.54 -15.718,-3.792 -13.705,-3.792
PIOBU6: "AB RoadRunner.J1-21" J3.15 | length 35.8
  Top Layer w0.2: -41.931,-3.81 -41.91,-3.81 -34.05,-3.81 -33.3,-3.06 -33.3,-0.67 -31.365,1.265 -22.785,1.265 -17.328,-4.192 -13.705,-4.192
  Top Layer w0.35: J3.15@-43.18,-5.08 -41.91,-3.81
PIOBU7: "AB RoadRunner.J1-23" J3.17 | length 35.3
  Top Layer w0.2: -41.945,-6.36 -41.92,-6.36 -33.17,-6.36 -32.04,-5.23 -32.04,-2.17 -31.12,-1.25 -22.52,-1.25 -19.19,-4.58 -13.705,-4.58
  Top Layer w0.35: J3.17@-43.18,-7.62 -41.92,-6.36
REFCLK0: L9.2 U2.14 | length 3.1
  Top Layer w0.3: L9.2@16.58,20.57 16.58,21.17 17.54,22.13 U2.14@17.54,22.815 ; U2.14@17.54,23.105 17.54,23.25 U2.14@17.54,23.31 ; U2.14@17.54,22.815 U2.14@17.54,23.105
RX_N: J11.6 R16.1 U2.22 | length 23.9
  Top Layer w0.178: U2.22@20.25,25.45 20.789,25.45 20.849,25.509 21.4,25.509 21.509,25.4 21.95,25.4 22.128,25.4 22.395,25.4 22.484,25.311 22.484,24.889 22.573,24.8 22.751,24.8 22.84,24.889 22.84,25.311 22.929,25.4 23.107,25.4 23.196,25.311 23.196,24.889 23.285,24.8 23.463,24.8 23.552,24.889 23.552,25.311 23.641,25.4 23.819,25.4 23.908,25.311 23.908,24.889 23.997,24.8 24.175,24.8 24.264,24.889 24.264,25.311 24.353,25.4 24.531,25.4 24.62,25.311 24.62,24.889 24.709,24.8 24.887,24.8 24.976,24.889 24.976,25.311 25.065,25.4 25.243,25.4 25.332,25.311 25.332,24.889 25.421,24.8 25.599,24.8 25.688,24.889 25.688,25.311 25.777,25.4 25.9,25.4 27.039,25.4 28.181,26.542 28.181,28.1 ; R16.1@29.1,28.65 29.1,28.2 29,28.1 28.181,28.1 ; J11.6@29.739,33.344 v2(29.739,31.9) 28.181,30.342 28.181,28.1
  Bottom Layer w0.178: v2(29.739,31.9) 29.739,33.344 J11.6@29.845,33.45
RX_P: J11.3 R15.1 U2.23 | length 24.1
  Top Layer w0.178: U2.23@20.25,25.95 20.789,25.95 20.849,25.89 21.558,25.89 21.667,25.781 26.881,25.781 27.8,26.7 27.8,28.1 ; R15.1@26.9,28.65 26.9,28.2 27,28.1 27.8,28.1 ; J11.3@33.39,35.99 v2(32.6,35.2) 32.1,34.7 29.1,34.7 28.6,34.2 28.6,31.3 27.8,30.5 27.8,28.1
  Bottom Layer w0.178: v2(32.6,35.2) 32.865,35.2 J11.3@33.655,35.99
SD_CLK: pad.9@-3.48,-33.96 U1.14 uSD.5 | length 19.3
  Top Layer w0.2: uSD.5@-5.08,-40.64 -3.94,-40.64 -2.68,-41.9 -1.79,-41.9 -0.96,-41.07 -0.96,-40.47 -0.96,-40.46 -1.06,-40.36 -1.11,-40.36 -1.21,-40.26 -1.21,-40.06 -1.11,-39.96 -0.96,-39.96 -0.81,-39.96 -0.71,-39.86 -0.71,-39.66 -0.81,-39.56 -0.96,-39.56 -1.11,-39.56 -1.21,-39.46 -1.21,-39.26 -1.11,-39.16 -0.96,-39.16 -0.81,-39.16 -0.71,-39.06 -0.71,-38.86 -0.81,-38.76 -0.96,-38.76 -1.11,-38.76 -1.21,-38.66 -1.21,-38.46 -1.11,-38.36 -0.96,-38.36 -0.81,-38.36 -0.71,-38.26 -0.71,-38.06 -0.81,-37.96 -0.96,-37.96 -1.11,-37.96 -1.21,-37.86 -1.21,-37.66 -1.11,-37.56 -0.96,-37.56 -0.81,-37.56 -0.71,-37.46 -0.71,-37.26 -0.81,-37.16 -0.86,-37.16 -0.96,-37.06 -0.96,-36.76 -0.96,-36.56 -1.212,-36.308 -1.424,-36.096 -1.565,-36.096 -1.601,-36.132 -1.742,-36.132 -1.883,-35.99 -1.883,-35.849 -1.777,-35.743 -1.671,-35.637 -1.671,-35.495 -1.813,-35.354 -1.954,-35.354 -2.06,-35.46 -2.166,-35.566 -2.308,-35.566 -2.449,-35.425 -2.449,-35.283 -2.343,-35.177 -2.237,-35.071 -2.237,-34.93 -2.378,-34.788 -2.52,-34.788 -2.555,-34.824 -2.697,-34.824 -2.909,-34.611 -3.05,-34.47 -3.05,-34.34 -3.05,-33.94 -3.05,-33.54 -3.05,-33.14 -3.05,-32.94 U1.14@-3.05,-31.97
SD_CMD: pad.9@-5.46,-33.56 U1.11 uSD.3 | length 16
  Top Layer w0.2: pad.9@-5.14,-33.53 -4.25,-32.64 U1.11@-4.25,-31.97
  Top Layer w0.25: v2(-5.29,-34.22) pad.9@-5.46,-33.56 pad.9@-5.14,-33.53
  Bottom Layer w0.25: v2(-5.29,-34.22) -5.19,-34.22 -5.14,-34.17 -4.73,-34.58 -4.73,-34.93 -4.73,-35.055 -4.605,-35.18 -4.455,-35.18 -4.33,-35.305 -4.33,-35.555 -4.455,-35.68 -4.73,-35.68 -5.005,-35.68 -5.13,-35.805 -5.13,-36.055 -5.005,-36.18 -4.73,-36.18 -4.455,-36.18 -4.33,-36.305 -4.33,-36.555 -4.455,-36.68 -4.73,-36.68 -5.005,-36.68 -5.13,-36.805 -5.13,-37.055 -5.005,-37.18 -4.73,-37.18 -4.7,-37.18 -4.575,-37.305 -4.575,-37.555 -4.7,-37.68 -4.73,-37.68 -5.005,-37.68 -5.13,-37.805 -5.13,-38.055 -5.005,-38.18 -4.73,-38.18 -4.68,-38.18 -4.555,-38.305 -4.555,-38.555 -4.68,-38.68 -4.73,-38.73 -4.73,-39.06 -4.73,-42.54 -4.44,-42.83 v2(-3.98,-42.83)
SD_DATA0: pad.9@-1.166,-33.386 U1.15 uSD.7 | length 15.3
  Top Layer w0.2: U1.15@-2.65,-31.97 -2.65,-32.426 v2@-2.026,-33.05
  Top Layer w0.25: v2@-2.026,-33.05 v2(-1.81,-33.05)
  Bottom Layer w0.25: v2(-3.911,-38.458) -3.692,-38.458 -3.68,-38.47 -3.435,-38.225 -3.367,-38.225 -3.03,-38.562 -2.853,-38.562 -2.676,-38.385 -2.676,-38.209 -3.047,-37.837 -3.23,-37.655 -3.23,-37.478 -3.053,-37.301 -2.876,-37.301 -2.694,-37.484 -2.323,-37.855 -2.146,-37.855 -1.969,-37.678 -1.969,-37.502 -2.252,-37.219 -2.252,-37.042 -1.987,-36.777 -1.81,-36.6 -1.81,-36.36 -1.81,-35.985 -1.935,-35.86 -2.335,-35.86 -2.46,-35.735 -2.46,-35.485 -2.335,-35.36 -1.81,-35.36 -1.285,-35.36 -1.16,-35.235 -1.16,-34.985 -1.285,-34.86 -1.81,-34.86 -2.335,-34.86 -2.46,-34.735 -2.46,-34.485 -2.335,-34.36 -1.81,-34.36 -1.285,-34.36 -1.16,-34.235 -1.16,-33.985 -1.285,-33.86 -1.685,-33.86 -1.81,-33.735 -1.81,-33.61 v2(-1.81,-33.05)
SD_DATA1: pad.9@-0.8,-31.8 U1.16 uSD.8 | length 16
  Top Layer w0.2: U1.16@-2.25,-32.09 -1.97,-32.37 v2(-1.35,-32.37)
  Top Layer w0.35: v2(-1.35,-32.37) -1.35,-32.35 pad.9@-0.8,-31.8
  Bottom Layer w0.25: v2(-3.947,-37.35) -3.925,-37.35 -3.045,-36.47 -3.045,-36.315 -3.045,-35.845 -3.015,-35.815 -2.89,-35.69 -2.89,-35.44 -3.015,-35.315 -3.045,-35.315 -3.67,-35.315 -3.795,-35.19 -3.795,-34.94 -3.67,-34.815 -3.045,-34.815 -3.015,-34.815 -2.89,-34.69 -2.89,-34.44 -3.015,-34.315 -3.045,-34.315 -3.071,-34.315 -3.196,-34.19 -3.196,-33.94 -3.071,-33.815 -3.045,-33.789 -3.045,-33.315 -3.045,-33.065 -3.54,-32.57 -4.21,-32.57 -4.53,-32.25 -4.53,-31.42 -4.19,-31.08 -3.21,-31.08 -3.074,-31.216 -2.809,-31.481 -2.809,-31.658 -3.162,-32.012 -3.162,-32.188 -2.985,-32.365 -2.809,-32.365 -2.455,-32.012 -2.278,-32.012 -2.19,-32.1 -1.92,-32.37 v2(-1.35,-32.37)
SD_DATA2: pad.9@-6.766,-32.186 U1.9 uSD.1 | length 17.4
  Top Layer w0.2: -5.2,-32.3 U1.9@-5.05,-32.15
  Top Layer w0.25: v2@-5.91,-32.24 -5.95,-32.28 -5.93,-32.3 -5.91,-32.3 -5.2,-32.3
  Top Layer w0.3: pad.9@-6.766,-32.186 -5.964,-32.186 v2@-5.91,-32.24
  Bottom Layer w0.25: v2(-5.91,-32.13) -5.91,-32.28 -6.614,-32.984 -7.001,-32.984 -7.355,-33.338 -7.355,-33.939 -6.806,-34.488 -6.806,-42.714 -4.47,-45.05 v2(-3.96,-45.05)
SD_DATA3: pad.9@-7.57,-33.51 U1.10 uSD.2 | length 17.2
  Top Layer w0.2: -4.96,-32.73 -4.65,-32.42 U1.10@-4.65,-31.97
  Top Layer w0.25: pad.9@-7.57,-33.51 -7.491,-33.589 v2(-6.75,-33.589) -5.896,-32.735 -5.659,-32.735 -5.654,-32.73 -4.96,-32.73
  Bottom Layer w0.25: v2(-6.75,-33.589) -6.75,-33.688 -6.12,-34.318 -6.12,-34.63 -6.12,-34.755 -5.995,-34.88 -5.845,-34.88 -5.72,-35.005 -5.72,-35.255 -5.845,-35.38 -6.12,-35.38 -6.16,-35.38 -6.285,-35.505 -6.285,-35.755 -6.16,-35.88 -6.12,-35.88 -5.845,-35.88 -5.72,-36.005 -5.72,-36.255 -5.845,-36.38 -6.12,-36.38 -6.16,-36.38 -6.285,-36.505 -6.285,-36.755 -6.16,-36.88 -6.12,-36.92 -6.12,-37.33 -6.12,-42.26 -4.45,-43.93 v2(-3.98,-43.93)
SDCLK: R24.2 U1.3 | length 13.5
  Top Layer w0.2: R24.2@-9.39,-22.49 -4.31,-22.49 -3.87,-22.93 -3.87,-27.59 -3.05,-28.41 U1.3@-3.05,-30.43
SHDN: "AB RoadRunner.J1-4" J1.1 J3.4 R29.1 | length 63.2
  Top Layer w0.2: -46.818,21.427 -43.691,18.3 -42.29,18.3 -40.2,16.21 -39.1,16.21 -38.121,15.231 -36.835,13.945 -36.835,10.937 -37.612,10.16 J3.4@-38.725,10.16 ; -44.979,22.877 -44.704,22.602 -44.024,22.602 -43.739,22.887 ; -43.739,22.888 -43.581,23.046 -43.581,23.575 R29.1@-43.584,23.578 ; v1@-11.4,-0.593 -10.595,-0.593
  Top Layer w0.3: -46.818,21.427 J1.1@-46.818,22.877 -44.979,22.877
  Bottom Layer w0.2: -38.866,10.186 -34.824,10.186 -30.53,14.48 -24.16,14.48 -21.608,11.928 -21.608,11.208 -11.4,1 v1(-11.4,-0.58)
  Bottom Layer w0.35: J3.4@-40.64,10.186 -38.866,10.186
TX_N: J11.2 R18.1 U2.20 | length 26.9
  Top Layer w0.178: U2.20@20.25,24.45 20.75,24.45 21.376,23.824 21.383,23.824 21.388,23.819 22.46,23.819 22.638,23.819 22.905,23.819 22.994,23.73 22.994,23.458 23.083,23.369 23.261,23.369 23.35,23.458 23.35,23.73 23.439,23.819 23.617,23.819 23.706,23.73 23.706,23.458 23.795,23.369 23.973,23.369 24.062,23.458 24.062,23.73 24.151,23.819 24.329,23.819 24.418,23.73 24.418,23.458 24.507,23.369 24.685,23.369 24.774,23.458 24.774,23.73 24.863,23.819 25.041,23.819 25.13,23.73 25.13,23.458 25.219,23.369 25.397,23.369 25.486,23.458 25.486,23.73 25.575,23.819 25.753,23.819 25.842,23.73 25.842,23.458 25.931,23.369 26.109,23.369 26.198,23.458 26.198,23.73 26.287,23.819 26.34,23.819 28.058,23.819 29.669,25.431 30.731,25.431 31.812,26.512 31.812,28.4 ; R18.1@32.55,28.4 31.812,28.4 ; J11.2@34.925,33.45 34.925,32.486 v2(34.5,32.061) 31.812,29.373 31.812,28.4
  Bottom Layer w0.178: v2(34.5,32.061) 34.925,32.486 J11.2@34.925,33.45
TX_P: J11.1 R17.1 U2.21 | length 27
  Top Layer w0.178: U2.21@20.25,24.95 20.789,24.95 21.534,24.205 21.541,24.205 21.546,24.2 27.9,24.2 29.512,25.812 30.573,25.812 31.431,26.669 31.431,28.1 ; R17.1@30.7,28.65 30.7,28.2 30.8,28.1 31.431,28.1 ; J11.1@36.195,35.99 35.205,35 v2(35.1,35) 34.8,35 34.5,34.7 34.1,34.7 33.7,34.3 33.7,31.8 31.431,29.531 31.431,28.1
  Bottom Layer w0.178: v2(35.1,35) 35.205,35 J11.1@36.195,35.99
UB_N: J7.2 LC1.2 | length 14
  Top Layer w0.22: LC1.2@-31.88,31.48 -31.88,31.84 -31.765,31.955 -31.765,34.955 -32.07,35.26 -32.07,37.21 -32.07,37.353 -31.223,38.2 -27.431,38.2 J7.2@-26.622,39.01
  Bottom Layer w0.22: v1(-28.15,38.35) -27.281,38.35 J7.2@-26.622,39.01
UB_P: J7.3 LC1.3 | length 13.9
  Top Layer w0.22: LC1.3@-31.28,31.48 -31.28,31.84 -31.395,31.955 -31.395,32.99 -31.395,33.21 -31.395,33.54 -31.285,33.65 -31.105,33.65 -30.995,33.76 -30.995,33.98 -31.105,34.09 -31.285,34.09 -31.395,34.2 -31.395,34.53 -31.395,34.57 -31.395,35.108 -31.7,35.413 -31.7,37.2 -31.07,37.83 -27.442,37.83 J7.3@-26.622,37.01
  Bottom Layer w0.22: v1(-28.14,37.68) -27.292,37.68 J7.3@-26.622,37.01
UC_N: J2.2 LC2.3 | length 10.6
  Top Layer w0.22: J2.2@-38.29,39.69 -38.29,39.23 -37.62,38.56 -36.58,38.56 -34.445,36.425 -34.38,36.36 -34.38,31.74 -34.34,31.7 LC2.3@-34.34,31.34
UC_P: J2.3 LC2.2 | length 10.6
  Top Layer w0.22: J2.3@-38.29,37.15 -38.29,37.52 -37.62,38.19 -36.733,38.19 -34.75,36.207 -34.75,33.34 -34.75,33.26 -34.86,33.15 -35.09,33.15 -35.2,33.04 -35.2,32.82 -35.09,32.71 -34.86,32.71 -34.75,32.6 -34.75,32.49 -34.75,31.73 -34.8,31.68 -34.8,31.48 LC2.2@-34.94,31.34
USB_5V: C8.1 F1.2 L1.1 | length 7.5
  Top Layer w0.5: L1.1@-22.11,30.95 -20.85,30.95 ; -19.6,30.95 -19.4,31.15 C8.1@-19.4,32.58
  Top Layer w1: -20.85,30.95 -19.6,30.95 F1.2@-16.295,30.95
USBA_ID: J5.1 J8.4 R6.2 | length 70.3
  Top Layer w0.3: v2@-17.1,36.85 v2(-17.1,36.9) -17.1,37.5 -15.773,38.827 -15.773,44.207 -15.51,44.47 J8.4@-15.51,46.33 ; R6.2@-7.66,24.13 -7.66,25.14 v3(-7.65,25.15) ; v2(20.22,14.63) 22.15,12.7 J5.1@23.485,12.7 24.1,12.7 J5.1@25.4,12.7
  Signal Layer 2 w0.3: v2@-17.12,36.87 -16.81,36.56 -16.81,30.22 -16.17,29.58 -16.17,25.69 -15,24.52 -13.817,24.52 -13.767,24.57 -7.65,24.57 -0.27,24.57 3.9,20.4 5.48,20.4 11.01,14.87 11.801,14.87 12.411,14.26 12.93,14.26 13.63,14.96 19.89,14.96 v2(20.22,14.63)
USBAF_N: J8.2 LC3.3 | length 9.8
  Top Layer w0.22: LC3.3@-14.24,36.66 -14.24,37.02 -14.355,37.135 -14.355,45.175 -14.21,45.32 J8.2@-14.21,46.33
USBAF_P: J8.3 LC3.2 | length 9.8
  Top Layer w0.22: J8.3@-14.86,46.33 -14.86,45.32 -14.725,45.185 -14.725,37.135 -14.84,37.02 LC3.2@-14.84,36.66
VBAT: "AB RoadRunner.J1-2" J3.2 pad.9@-39.82,17.78 R33.2 | length 48.6
  Top Layer w0.2: -10.595,-0.192 v1@-9.742,-0.192
  Top Layer w0.3: v4@-39.06,17.82 R33.2@-38.3,17.82
  Top Layer w0.4: v4(-39.08,17.8) v4@-39.06,17.82
  Signal Layer 2 w0.4: J3.2@-40.64,12.7 -39.08,14.26 v4(-39.08,17.8)
  Bottom Layer w0.2: -38.873,12.67 -36.86,12.67 -34.14,15.39 -23.945,15.39 -20.895,12.34 -20.553,12.34 -20.02,11.807 -20.02,11.465 -19.725,11.17 -19.413,11.17 -18.88,10.637 -18.88,10.325 -17.905,9.35 -17.493,9.35 -16.96,8.817 -16.96,8.763 -16.177,7.98 -15.983,7.98 -15.365,7.362 -15.365,6.424 -14.183,5.242 -12.095,5.242 -11.02,4.167 -11.02,2.3 -9.74,1.02 v1(-9.74,-0.19)
  Bottom Layer w0.35: J3.2@-40.64,12.67 -38.873,12.67
WKUP: "AB RoadRunner.J1-6" J3.1 | length 44.7
  Top Layer w0.2: -10.595,-0.992 v1@-9.742,-0.992
  Bottom Layer w0.2: -41.708,11.44 -36.87,11.44 -36.12,12.19 -34.45,12.19 -31.67,14.97 -24.062,14.97 -21.052,11.96 -20.71,11.96 -20.4,11.65 -20.4,11.308 -19.882,10.79 -19.57,10.79 -19.26,10.48 -19.26,10.168 -18.062,8.97 -17.65,8.97 -17.34,8.66 -17.34,8.606 -16.334,7.6 -16.14,7.6 -15.799,7.259 -15.799,6.159 -10.862,1.222 -10.618,1.222 -10.29,0.894 -10.29,-0.44 v1(-9.74,-0.99)
  Bottom Layer w0.35: J3.1@-43.074,12.806 -41.708,11.44
pads on no net: "Fid 1.FID" "Fid 2.FID" "Fid 3.FID" "Fid 4.FID" J7.7 J7.8 J10.1 J10.2 J10.5 J11.7 J11.MH3 J11.MH4 U1.4 U1.5 U1.13
copper on no net:
  other v7: 16.82,41.92 -3.2,43.72 7.92,43.82

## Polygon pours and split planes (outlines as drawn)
EARTH1 on Top Layer "Top EARTH1" (solid, remove dead copper, pour order 50): 48.48,49.28 16.3,49.28 16.21,49.19 15.72,48.7 15.72,46.28 15.72,40.77 18,38.49 18.37,38.12 43.93,38.12 48.11,38.12 48.48,38.49
3V3 on Top Layer "Top 3V3_1" (solid, remove dead copper, pour order 44): -8.21,22.53 -7.43,23.31 -7.4,23.34 -4.65,23.34 -4.61,23.34 -4.33,23.06 -4.25,22.98 -4.25,21.17 -4.25,20.2 -3.69,19.64 -3.62,19.57 -3.62,19.03 -3.62,18.25 -3.3,17.93 -2.96,17.59 -0.99,17.59 0.5,17.59 1.15,18.24 1.5,18.59 2.9,18.59 2.99,18.59 3.24,18.34 3.4,18.18 3.4,16.32 3.38,16.32 2.97,15.91 2.28,15.22 2.28,14.25 2.28,13.99 2.04,13.75 1.85,13.56 1.33,13.56 -1.72,13.56 -2.44,14.28 -3.48,15.32 -4.5,15.32 -8.28,15.32 -8.88,15.92 -10.26,17.3 -10.26,18.11 -10.26,18.42 -9.78,18.9 -9.71,18.97 -8.94,18.97 -8.73,18.97 -8.21,19.241
GND on Top Layer "Top Layer-GND" (solid, remove dead copper, pour order 63): -48.006,36.39 -24.8,36.39 -21.83,39.36 19.2,39.36 22.17,36.39 48.01,36.39 48.01,-47.982 -47.988,-47.982 -47.998,-47.972
IN_5V on Top Layer "Top In5V " (solid, pour order 49): -13.42,32.953 -13.42,35.03 -10.56,35.03 -6.593,32.954 -6.08,32.441 -6.08,29.826 -6.08,25.375 -6.391,25.064 -11.53,25.063 -11.53,28.49 -13.42,28.49
EARTH2 on Top Layer "Top Earth2" (solid, pour order 46): -47.98,38.16 -47.98,48.388 -9.132,48.388 -9.101,48.354 -9.083,48.334 -9.083,46.876 -9.241,46.876 -11.535,44.393 -11.55,44.378 -18.461,44.378 -21.056,41.57 -32.94,41.57 -33.205,41.835 -35.12,43.75 -41.17,43.75 -42.18,42.74 -42.18,41.97 -43.25,40.9 -43.25,38.16
IN_GND on Top Layer "Top IN_GND" (solid, pour order 57): -19.823,40.098 -19.799,40.098 -17.595,42.005 -17.597,42.007 -17.597,43.092 -17.597,44.315 -17.063,44.777 -17.039,44.777 -16.196,44.777 -16.125,44.716 -15.983,44.593 -15.983,39.588 -15.983,39.403 -17.502,38.088
EARTH1 on Bottom Layer "Bot EARTH1" (solid, remove dead copper, pour order 73): 48.48,49.28 16.3,49.28 16.21,49.19 15.72,48.7 15.72,46.28 15.72,40.77 18,38.49 18.37,38.12 43.93,38.12 48.11,38.12 48.48,38.49
IN_5V on Bottom Layer "Bottom In_5V" (solid, pour order 59): -8.069,24.731 -10.888,24.713 -10.888,32.954 -10.888,37.618 -11.013,37.618 -13.42,39.342 -13.744,39.666 -13.744,45.067 -12.151,45.067 -11.745,44.662 -11.745,40.575 -9.033,38.717 -6.593,32.954 -6.633,24.727
EARTH2 on Bottom Layer "Bottom Earth2" (solid, pour order 58): -47.98,41.54 -47.98,48.822 -9.137,48.822 -9.106,48.784 -9.088,48.762 -9.088,44.664 -9.368,44.324 -18.728,44.324 -21.02,41.54 -32.95,41.54 -35.13,43.72 -41.16,43.72 -42.145,42.735 -42.145,41.95 -43.232,40.862 -43.232,38.65 -47.98,38.65
GND on Bottom Layer "Bottom Layer-GND" (solid, remove dead copper, pour order 65): -48.006,36.81 4160.761,36.945 48.01,38.33 48.01,-47.981 -47.988,-47.981 -47.998,-47.972
NRST on Signal Layer 2 "MID2NRST" (solid, remove dead copper, pour order 71): -8.908,-4.056 -8.885,-4.033 -7.277,-4.033 -7.277,-5.636 -7.307,-5.666
IN_5V on Signal Layer 2 "MID2 IN_5V" (solid, remove dead copper, pour order 61): -11.73,24.82 -6.68,24.82 -6.68,36.43 -10.81,40.56 -11.32,41.07 -11.32,43.36 -11.32,44.29 -11.9,44.87 -12.17,45.14 -12.5,45.14 -12.73,45.14 -13.18,44.69 -13.77,44.1 -13.77,40.59 -13.77,29.44 -12.18,27.85 -11.77,27.44 -11.77,27
GND on Signal Layer 2 "MID2GND" (solid, remove dead copper, pour order 69): -48.831,36.33 48.14,36.33 49.01,37.2 48.66,36.85 48.66,-48.41 -48.69,-48.41 -48.91,-48.19
GND on Signal Layer 1 "MID1 GND" (solid, remove dead copper, pour order 67): -48.162,36.33 48.43,36.33 48.43,-48.25 48.55,-48.37 48.39,-48.21 -48.36,-48.21

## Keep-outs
Keep-Out Layer:
  lines w0.3: -49.107,-48.692 -49.107,48.708 -22.348,48.708 -21.188,49.868 -8.414,49.868 -7.066,48.52 12.858,48.52 13.379,49.041 24.291,49.041 24.807,49.557 49.639,49.557 49.639,-48.692 -49.107,-48.692

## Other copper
Top Layer:
  pour cut-out: -12.683,45.237 -12.563,45.118 -12.023,45.118 -11.852,44.947 -11.852,44.907 -11.703,44.758 -11.703,44.328 -11.593,44.218 -11.073,44.218 -11.053,44.238 -10.723,44.238 -10.723,44.328 -10.573,44.478 -10.573,45.208 -10.603,45.238 -12.117,45.769
  pour cut-out: -12.683,46.317 -12.683,45.237 -13.573,44.867 -13.673,44.698 -13.673,44.398 -16.202,44.435 -16.196,44.777 -17.223,44.777 -17.591,44.268 -17.833,43.838 -18.103,44.108 -18.103,46.247 -18.013,46.337
  pour cut-out: -17.583,44.268 -17.583,42.178 -18.363,41.398 -18.363,41.278 -22.063,37.578 -22.913,37.578 -22.913,39.498 -21.343,41.067 -19.473,42.437 -17.703,42.87 -17.703,44.148
  pour cut-out: 23.56,32.31 39.93,32.31 39.97,32.35 39.92,32.4 39.92,51.15 23.44,51.15 23.39,51.2 23.53,51.2
Signal Layer 1:
  pour cut-out: 23.56,32.31 39.93,32.31 39.97,32.35 39.92,32.4 39.92,51.15 23.44,51.15 23.39,51.2 23.53,51.2
Signal Layer 2:
  pour cut-out: 23.56,32.31 39.93,32.31 39.97,32.35 39.92,32.4 39.92,51.15 23.44,51.15 23.39,51.2 23.53,51.2
Bottom Layer:
  pour cut-out: 23.44,51.1 23.55,50.99 23.55,32.33 39.55,32.33 39.95,32.33 39.95,51.18
  pour cut-out: -13.291,46.31 -12.563,45.118 -12.023,45.118 -11.852,44.947 -11.852,44.907 -11.703,44.758 -11.703,44.328 -11.593,44.218 -11.073,44.218 -11.053,44.238 -10.27,44.237 -10.27,45.06 -10.904,45.694 -12.661,46.31
  pour cut-out: -12.683,46.317 -12.683,45.237 -13.244,44.676 -13.244,44.472 -13.488,44.472 -13.573,44.388 -13.583,44.398 -16.803,44.398 -16.973,44.228 -16.973,43.898 -17.063,43.807 -17.833,43.807 -18.453,44.208 -18.453,45.897 -18.013,46.337
  pour cut-out: -16.093,44.548 -16.103,44.538 -16.103,43.137 -17.343,41.898 -17.863,41.898 -18.363,41.398 -18.372,41.271 -18.59,41.052 -21.413,38.288 -22.913,36.435 -22.913,39.498 -21.343,41.067 -20.103,42.297 -17.343,42.957 -17.343,44.148 -17.323,44.148 -16.873,44.598

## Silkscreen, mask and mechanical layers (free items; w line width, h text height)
Top Overlay:
  lines w0.1: -5.55,-32.6 -4.87,-32.6
  lines w0.2: -13,-25.4 -13.02,-25.38 -13.02,-17.78 -11.12,-17.78 ; -10.8,-26.2 -6.8,-26.2 -6.8,-17.8 -6.82,-17.78 -9.98,-17.78 ; -7.81,-32.65 -7.39,-32.65 -6.9,-33.14 -6.01,-33.14 ; -7.08,-17.24 -7.05,-17.27 7.26,-17.27 7.26,-2.79 -7.08,-2.79 -7.08,-17.24 ; -5.7,-27.9 -5.7,-19.6 8.9,-19.6 8.9,-27.9 -5.7,-27.9
  text "HSIC" at -40.21,44.74 h2
  text "3V3OUT" at -36.58,41.83 h1.5
  text "GND" at -42.74,34.15 h1.5
  text "DEBUG PORT" at -4.37,31.89 h2.5
  text "+5V" at -48,29.54 h1.5
  text "3V3OUT" at 42.69,28.53 h1.2
  text "In 5V" at -10.78,28.31 h2
  text "GND" at -3.01,28.22 h1.5 r90
  text "RXD" at 1.97,28.22 h1.5 r90
  text "TXD" at 4.6,28.22 h1.5 r90
  text "EN3V" at -45.22,25.13 h1.5
  text "Berta D2" at -34.18,24.34 h5
  text "3V3ETH" at 39.72,24.07 h1.2
  text "GND" at -15.9,23.46 h2
  text "rel. 1.0" at -30.29,22.29 h2
  text "SHDN" at -48.13,20.21 h1.5
  text "www.acmesystems.it" at -37.94,20.18 h2.5
  text "VBAT" at -42.24,18.61 h1.5
  text "3V3" at 43.9,17.94 h1.2
  text "3V3IN" at 6.3,17.22 h1.2
  text "3V3" at -1.32,17.1 h1.2
  text "ENABLE" at 29.8,15.35 h1.5
  text "VBAT_SC" at -37.67,15.04 h1.5
  text "ETHN" at 30.33,14.11 h1.5
  text "VBAT" at -37.593,12.942 h1.5
  text "PB13" at 31,12.44 h1.5
  text "WKUP" at -49.87,12.29 h1.4
  text "3V3" at 46.39,12.281 h1.5
  text "PB30" at -22.184,12.239 h1.5
  text "USBAID" at 17.355,12.208 h1.5
  text "PB31" at -33.949,11.723 h1.5
  text "PD19" at 34.34,11.623 h1.5
  text "SHDN" at -37.593,10.401 h1.5
  text "COMP" at -49.85,10.36 h1.4
  text "GND" at 30.971,10.366 h1.5
  text "PB28" at -22.227,9.771 h1.5
  text "3V3" at 46.39,9.741 h1.5
  text "PB11" at 19.243,9.668 h1.5
  text "P" at -47.06,9.17 h1.4
  text "PB29" at -34.136,9.163 h1.5
  text "PD20" at 34.343,9.003 h1.5
  text "BURXD" at -37.593,7.861 h1.5
  text "PB12" at 30.971,7.826 h1.5
  text "COMP" at -49.922,7.52 h1.4
  text "PC9" at 46.39,7.201 h1.5
  text "PB26" at -22.184,7.159 h1.5
  text "PB4" at 19.808,7.128 h1.5
  text "PB27" at -34.133,6.573 h1.5
  text "PD21" at 34.489,6.323 h1.5
  text "N" at -46.96,6.3 h1.4
  text "PD23" at -37.593,5.321 h1.5
  text "PB5" at 30.971,5.286 h1.5
  text "PB24" at -22.248,4.873 h1.5
  text "GND" at 46.39,4.661 h1.5
  text "GND" at -49.142,4.611 h1.5
  text "PB3" at 19.804,4.588 h1.5
  text "PB25" at -34.141,4.093 h1.5
  text "PD22" at 34.349,3.813 h1.5
  text "RoadRunner" at -9.55,3.29 h4
  text "PD29" at -37.593,2.781 h1.5
  text "GND" at 30.971,2.746 h1.5
  text "PB7" at 46.39,2.121 h1.5
  text "PD24" at -49.42,2.071 h1.5
  text "BU5" at -22.184,2.079 h1.5
  text "PB2" at 19.814,2.048 h1.5
  text "BU4" at -33.464,1.563 h1.5
  text "PB8" at 34.995,1.443 h1.5
  text "PD30" at -37.593,0.241 h1.5
  text "PB1" at 30.971,0.206 h1.5
  text "PB6" at 46.39,-0.419 h1.5
  text "PD28" at -49.425,-0.469 h1.5
  text "PD25" at -22.184,-0.461 h1.5
  text "PD4" at 19.733,-0.492 h1.5
  text "JTAGSL" at -35.657,-1.011 h1.5
  text "PB9" at 34.995,-1.097 h1.5
  text "PD31" at -37.593,-2.299 h1.5
  text "PC31" at 30.971,-2.334 h1.5
  text "PB10" at 46.39,-2.959 h1.5
  text "BU2" at -48.823,-3.009 h1.5
  text "GND" at -22.184,-3.001 h1.5
  text "PC30" at 18.986,-3.032 h1.5
  text "PD26" at -34.208,-3.597 h1.5
  text "PC28" at 34.34,-3.757 h1.5
  text "GND" at -37.593,-4.839 h1.5
  text "PC14" at 30.971,-4.874 h1.5
  text "GND" at 46.39,-5.499 h1.5
  text "BU6" at -48.831,-5.549 h1.5
  text "PD27" at -22.184,-5.541 h1.5
  text "PC15" at 18.976,-5.572 h1.5
  text "PC5" at -33.47,-6.077 h1.5
  text "PC29" at 34.34,-6.267 h1.5
  text "BU3" at -37.593,-7.379 h1.5
  text "PC12" at 30.971,-7.414 h1.5
  text "WARNING !" at -4.49,-7.92 h2
  text "PD1" at 46.39,-8.039 h1.5
  text "BU7" at -48.831,-8.089 h1.5
  text "PC6" at -22.184,-8.081 h1.5
  text "PC13" at 18.983,-8.112 h1.5
  text "PC7" at -33.462,-8.617 h1.5
  text "PD5" at 34.931,-8.717 h1.5
  text "PA2" at -37.593,-9.919 h1.5
  text "PC10" at 30.971,-9.954 h1.5
  text "CHECK" at -2,-10.2 h1.5
  text "PD0" at 46.39,-10.579 h1.5
  text "PC8" at -48.829,-10.629 h1.5
  text "PA0" at -22.184,-10.621 h1.5
  text "PC11" at 19.168,-10.652 h1.5
  text "GND" at -33.857,-11.147 h1.5
  text "GND" at 34.622,-11.267 h1.5
  text "PA4" at -37.593,-12.459 h1.5
  text "PC20" at 30.971,-12.494 h1.5
  text "PD12" at 46.39,-13.119 h1.5
  text "PA7" at -48.767,-13.169 h1.5
  text "GND" at -22.184,-13.161 h1.5
  text "PC21" at 19.168,-13.192 h1.5
  text "PC4" at -33.459,-13.697 h1.5
  text "PD14" at 34.344,-13.937 h1.5
  text "CPU" at 1.9,-14.4 h2 r180
  text "Mounting Position" at -5.5,-14.5 h1.5
  text "PA3" at -37.593,-14.999 h1.5
  text "PC18" at 30.971,-15.034 h1.5
  text "PD9" at 46.39,-15.659 h1.5
  text "PA26" at -49.361,-15.709 h1.5
  text "PC2" at -22.184,-15.701 h1.5
  text "PC19" at 18.981,-15.732 h1.5
  text "PC3" at -33.462,-16.237 h1.5
  text "PD17" at 34.341,-16.557 h1.5
  text "PA10" at -37.593,-17.539 h1.5
  text "PC16" at 30.971,-17.574 h1.5
  text "PD13" at 46.39,-18.199 h1.5
  text "PA29" at -49.365,-18.249 h1.5
  text "PC1" at -22.184,-18.241 h1.5
  text "PC17" at 18.983,-18.272 h1.5
  text "PA5" at -33.395,-18.777 h1.5
  text "PD15" at 34.336,-19.007 h1.5
  text "PA30" at -49.4,-19.99 h1.5
  text "PA1" at -37.593,-20.079 h1.5
  text "PC26" at 30.971,-20.114 h1.5
  text "PD8" at 46.39,-20.739 h1.5
  text "PC0" at -22.184,-20.781 h1.5
  text "PC27" at 18.983,-20.812 h1.5
  text "NC" at -32.801,-21.317 h1.5
  text "CD" at -48.93,-21.38 h1.8
  text "PD16" at 34.341,-21.547 h1.5
  text "PA23" at -37.593,-22.619 h1.5
  text "PC24" at 30.971,-22.654 h1.5
  text "PD10" at 46.39,-23.279 h1.5
  text "GND" at -49.142,-23.329 h1.5
  text "PC25" at 18.976,-23.352 h1.5
  text "PA6" at -22.237,-23.45 h1.5
  text "QSPI" at -7.6,-23.7 h2 r180
  text "DDR" at 3.2,-23.7 h2 r180
  text "GND" at -33.857,-23.947 h1.5
  text "PD11" at 34.489,-24.117 h1.5
  text "PB0" at -37.593,-25.159 h1.5
  text "PC22" at 30.971,-25.194 h1.5
  text "PD7" at 46.39,-25.819 h1.5
  text "PA14" at -49.36,-25.869 h1.5
  text "PA8" at -22.184,-25.861 h1.5
  text "PC23" at 18.983,-25.892 h1.5
  text "NC" at -32.801,-26.397 h1.5
  text "PD6" at 34.937,-26.497 h1.5
  text "PA24" at -37.593,-27.699 h1.5
  text "3V3" at 46.354,-27.707 h1.5
  text "NC" at 30.971,-27.734 h1.5
  text "PA15" at -49.369,-28.409 h1.5
  text "PA11" at -22.184,-28.401 h1.5
  text "PD18" at 18.983,-28.512 h1.5
  text "PA9" at -33.39,-28.937 h1.5
  text "OUT" at 46.233,-28.983 h1.5
  text "URXD1" at 33.537,-29.187 h1.5
  text "PA31" at -37.593,-30.239 h1.5
  text "GND" at 30.971,-30.274 h1.5
  text "3V3" at 46.382,-30.309 h1.5
  text "PA27" at -49.363,-30.949 h1.5
  text "PA13" at -22.184,-30.941 h1.5
  text "NC" at 20.39,-31.052 h1.5
  text "PA12" at -34.123,-31.477 h1.5
  text "D2" at -7.8,-31.5 h1.5
  text "UTXD1" at 33.5,-31.6 h1.5
  text "OUT" at 46.291,-31.608 h1.5
  text "D1" at 0,-32.3 h1.5
  text "PA25" at -37.593,-32.779 h1.5
  text "CMD" at -11.01,-32.83 h1.5
  text "FU2V5" at 30.971,-32.814 h1.5
  text "BOOT" at -49.808,-32.878 h1.5
  text "EN" at 46.34,-33.19 h1.5
  text "CLK" at -4.64,-33.42 h1.5
  text "PA17" at -22.184,-33.481 h1.5
  text "NC" at 20.39,-33.592 h1.5
  text "D0" at -0.4,-33.8 h1.5
  text "PA16" at -34.133,-34.017 h1.5
  text "NC" at 35.465,-34.117 h1.5
  text "D3" at -9.72,-34.19 h1.5
  text "OFF" at -48.799,-34.247 h1.5
  text "ETHN" at 46.32,-34.49 h1.5
  text "GND" at -37.593,-35.319 h1.5
  text "GND" at 30.87,-35.35 h1.5
  text "GND" at 46.39,-35.979 h1.5
  text "GND" at -49.142,-36.029 h1.5
  text "GND" at -22.184,-36.021 h1.5
  text "GND" at 19.334,-36.052 h1.5
  text "GND" at -33.857,-36.567 h1.5
  text "GND" at 34.88,-36.85 h1.5
  text "3V3OUT" at -18.9,-37.1 h1.5
  text "GND" at -41.12,-43.06 h2.3
  text "GND" at 33.1,-43.17 h2.3
  text "3V3OUT" at 27.82,-46.1 h1.5
  text "BOOTOFF" at -32.22,-46.7 h1.5
  text "RESET" at 16.4,-47.96 h1.5
Top Solder:
  lines w0.3: -50.193,-49.993 50.31,-49.99 50.307,50.01 -50.19,50.007 -50.193,-49.99
  text "B" at -46.799,16.162 h1.8
  text "OB" at -46.586,16.162 h1.8
Bottom Solder:
  lines w0.2: 9.932,-41.586 9.932,-41.267 18.742,-41.267 18.742,-46.426 9.932,-46.426 9.932,-41.446
  lines w0.5: -50.193,-49.993 50.31,-49.99 50.307,50 -50.19,50.008 -50.193,-49.99
  text "ACME" at 18.012,-44.016 h2
  text "SYSTEMS" at 17.982,-45.866 h1.1
Mechanical 1:
  lines w0.1: -50.193,-49.992 -50.193,-48.992 -50.193,49.008 -50.193,50.008 -49.193,50.008 49.307,50.007 50.307,50.007 50.307,49.007 50.307,-48.992 50.307,-49.992 49.307,-49.992 -49.193,-49.992 -50.193,-49.992
Mechanical 2:
  lines w0.3: -26.492,-29.034 -26.492,23.966 26.508,23.966 26.508,-29.034
Mechanical 15:
  lines w0.05: -49.993,-49.993 49.992,49.992 ; -49.985,49.997 49.996,-49.983

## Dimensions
-50.193,-49.992 to -49.193,50.007 on Mechanical 2
-50.193,-48.992 to 50.307,-48.992 on Mechanical 2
